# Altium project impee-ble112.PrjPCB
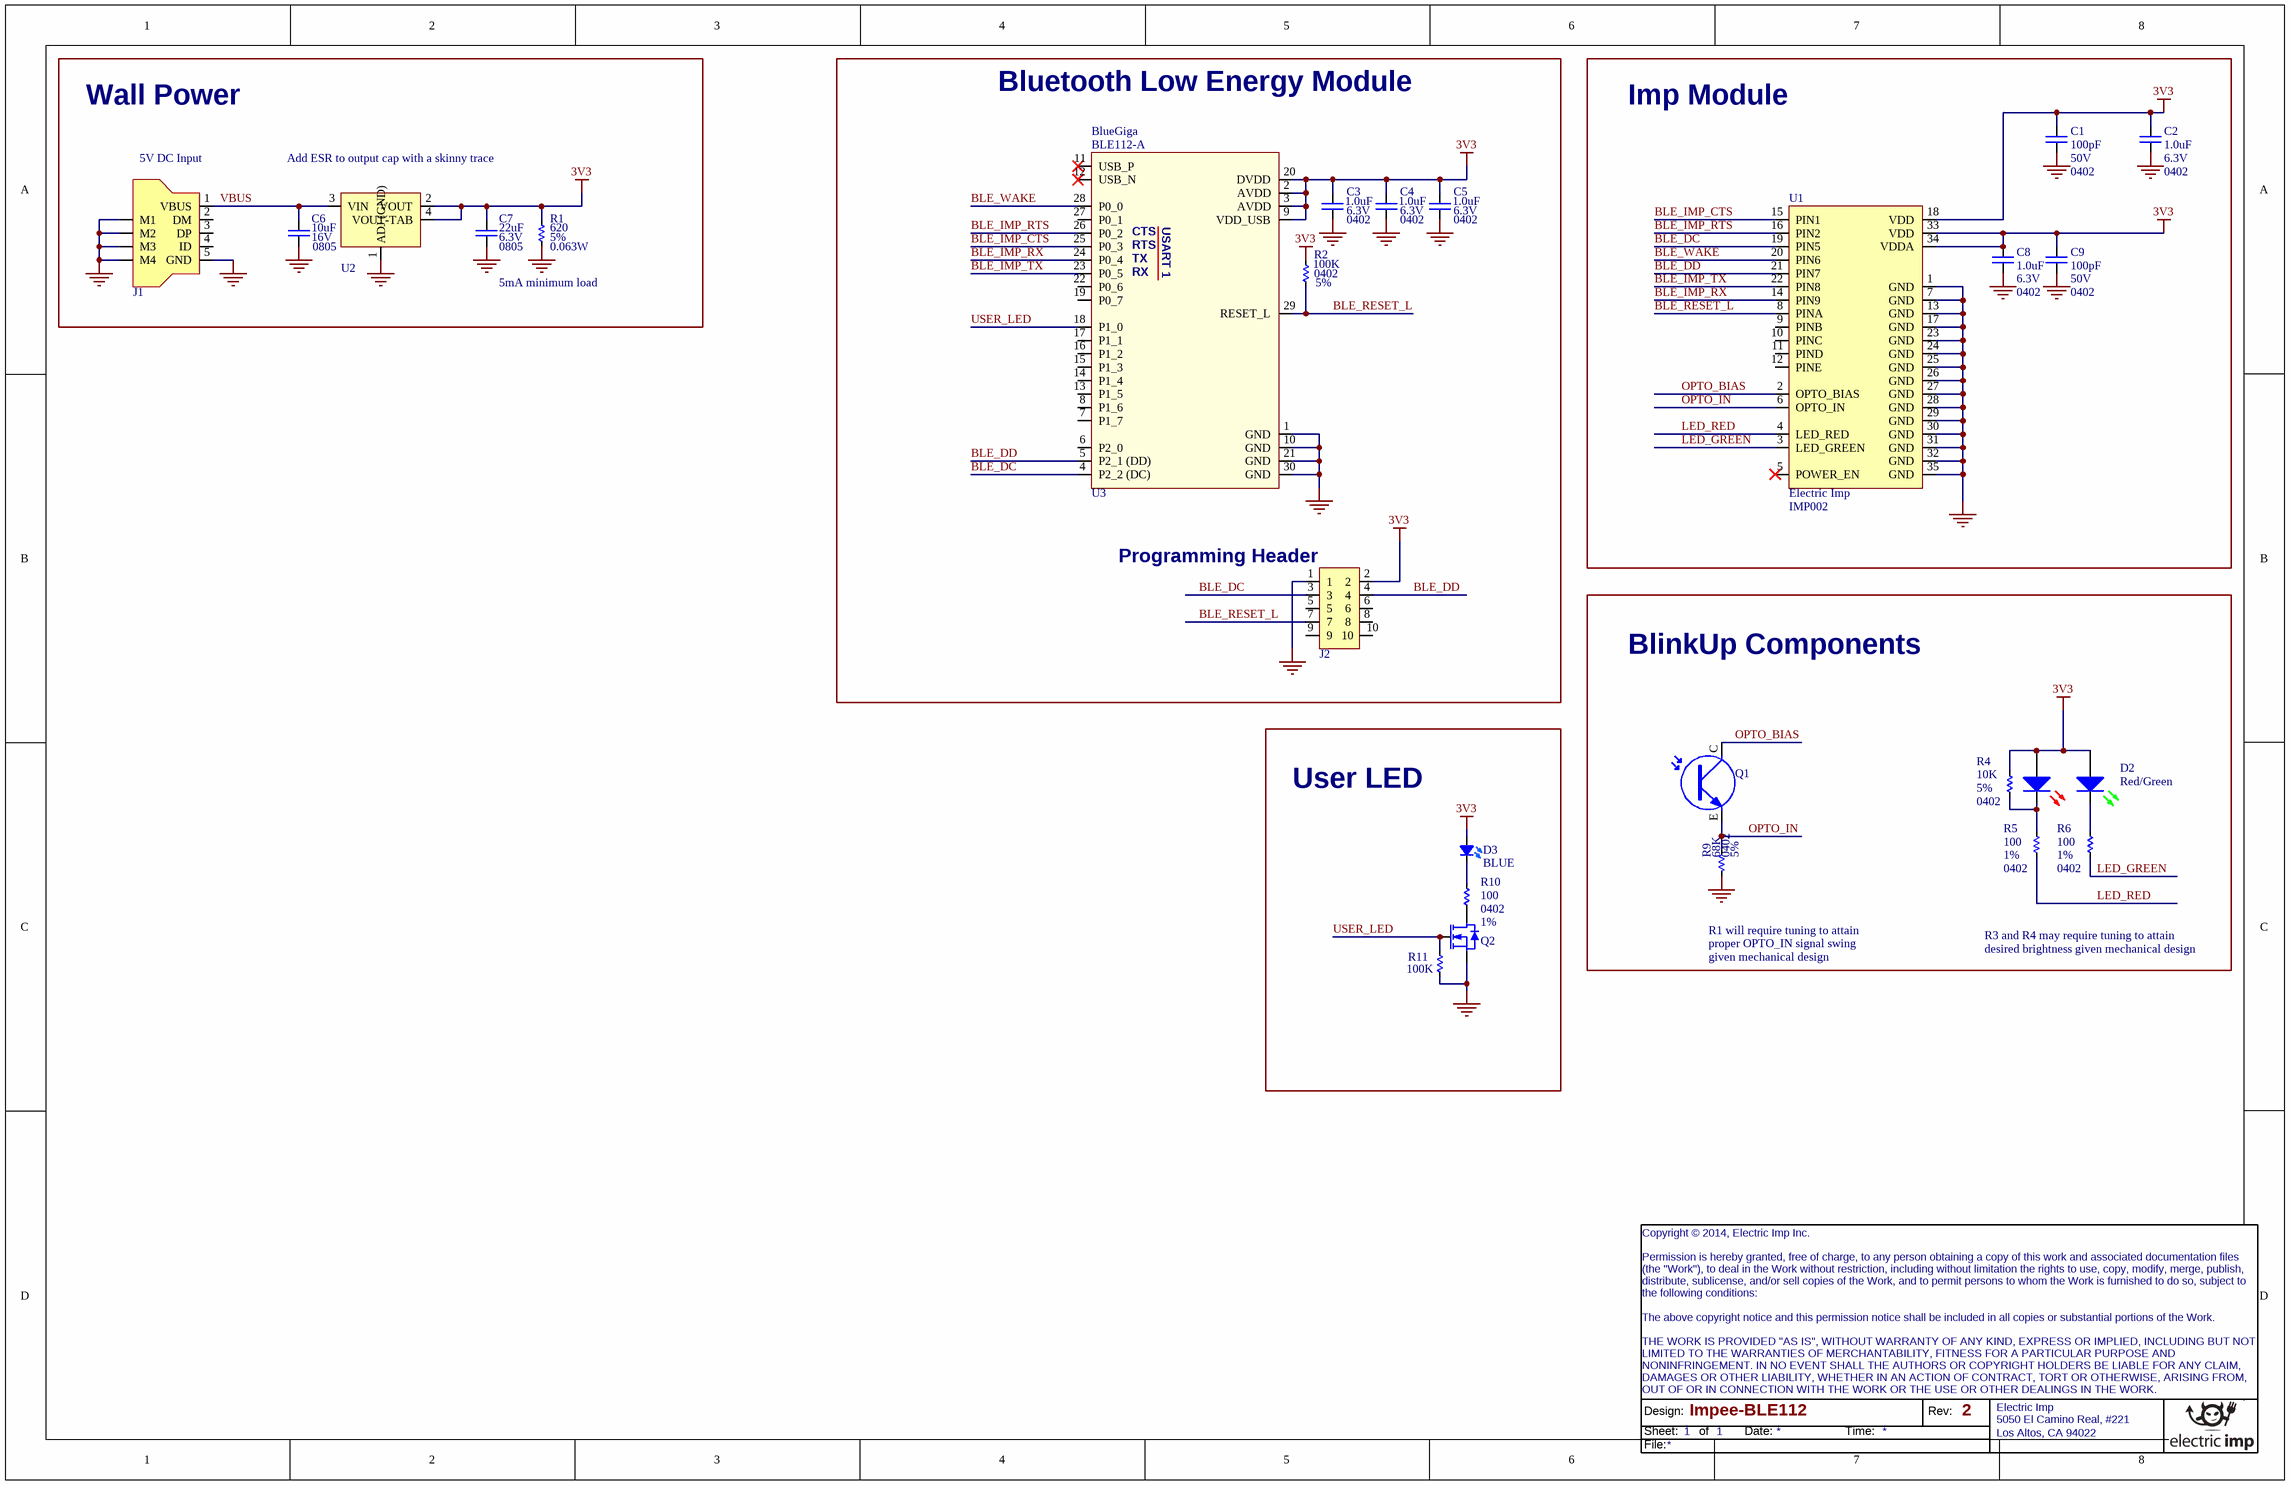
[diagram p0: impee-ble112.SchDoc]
1 sheet, 26 parts. Net scope: global (net labels, ports and power ports of the same name join across sheets).
Board file: impee-ble112.PcbDoc

## Sheet impee-ble112.SchDoc: Impee-BLE112
size Tabloid; Revision: 2; SheetNumber: 1; SheetTotal: 1

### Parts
C1  value 100pF  Voltage: 50V  Package: 0402  [CAPC1005X07N]  (hidden comment: Ceramic Capacitor)
C2  value 1.0uF  Voltage: 6.3V  Package: 0402  [CAPC1005X07N]  (hidden comment: Ceramic Capacitor)
C3  value 1.0uF  Voltage: 6.3V  Package: 0402  [CAPC1005X07N]  (hidden comment: Ceramic Capacitor)
C4  value 1.0uF  Voltage: 6.3V  Package: 0402  [CAPC1005X07N]  (hidden comment: Ceramic Capacitor)
C5  value 1.0uF  Voltage: 6.3V  Package: 0402  [CAPC1005X07N]  (hidden comment: Ceramic Capacitor)
C6  value 10uF  Voltage: 16V  Package: 0805  [CAPC2012X14N]  (hidden comment: Ceramic Capacitor)
C7  value 22uF  Voltage: 6.3V  Package: 0805  [CAPC2012X14N]  (hidden comment: Ceramic Capacitor)
C8  value 1.0uF  Voltage: 6.3V  Package: 0402  [CAPC1005X07N]  (hidden comment: Ceramic Capacitor)
C9  value 100pF  Voltage: 50V  Package: 0402  [CAPC1005X07N]  (hidden comment: Ceramic Capacitor)
D2  Color: Red/Green  [LED1616X07N-REDGREEN]  (hidden comment: LED Red and Green)
D3  Color: BLUE  [LED1608X08N-BLUE]  (hidden comment: LED Blue)
J1  USB Mini/Micro-B  [4UCON20035]  (value not drawn)
J2  Header  [HDR127P2X5-N]  (value not drawn)
Q1  PHOTOTRANSISTOR  [PHOTOTRANS2012X13]  (value not drawn)
Q2  N-Channel MOSFET  [SOT95P300X130-3N]  (value not drawn)
R1  value 620  Tolerance: 5%  Power: 0.063W  [RESC1005X04N]  (hidden comment: Resistor)
R2  value 100K  Package: 0402  Tolerance: 5%  [RESC1005X04N]  (hidden comment: Resistor)
R4  value 10K  Package: 0402  Tolerance: 5%  [RESC1005X04N]  (hidden comment: Resistor)
R5  value 100  Package: 0402  Tolerance: 1%  [RESC1005X04N]  (hidden comment: Resistor)
R6  value 100  Package: 0402  Tolerance: 1%  [RESC1005X04N]  (hidden comment: Resistor)
R9  value 68K  Package: 0402  Tolerance: 5%  [RESC1005X04N]  (hidden comment: Resistor)
R10  value 100  Package: 0402  Tolerance: 1%  [RESC1005X04N]  (hidden comment: Resistor)
R11  value 100K  [RESC1005X04N]  (hidden comment: Resistor)
U1  Manufacturer: Electric Imp  Manufacturer Part Number: IMP002  [IMP_MODULE]  (hidden comment: imp module)
U2  AP1117  [SOT230P700X180-4N]  (value not drawn)
U3  Manufacturer: BlueGiga  Manufacturer Part Number: BLE112-A  [BLE112]  (hidden comment: BLE112)

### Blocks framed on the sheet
Wall Power: C6 C7 J1 R1 U2
Bluetooth Low Energy Module: C3-C5 J2 R2 U3
Imp Module: C1 C2 C8 C9 U1
BlinkUp Components: D2 Q1 R4-R6 R9
User LED: D3 Q2 R10 R11

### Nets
3V3: C1.2 C2.2 C3.2 C4.2 C5.2 C7.2 C8.2 C9.2 D2.AG D2.AR D3.A J2.2 R1.2 R2.2 R4.2 U1.18(VDD) U1.33(VDD) U1.34(VDDA) U2.2(VOUT) U2.4(VOUT-TAB) U3.2(AVDD) U3.3(AVDD) U3.9(VDD_USB) U3.20(DVDD)
GND: C1.1 C2.1 C3.1 C4.1 C5.1 C6.1 C7.1 C8.1 C9.1 J1.5(GND) J1.M1 J1.M2 J1.M3 J1.M4 J2.1 Q2.2(S) R1.1 R9.1 R11.1 U1.1(GND) U1.7(GND) U1.13(GND) U1.17(GND) U1.23(GND) U1.24(GND) U1.25(GND) U1.26(GND) U1.27(GND) U1.28(GND) U1.29(GND) U1.30(GND) U1.31(GND) U1.32(GND) U1.35(GND) U2.1(ADJ_(GND)) U3.1(GND) U3.10(GND) U3.21(GND) U3.30(GND)
BLE_DC: J2.3 U1.19(PIN5) U3.4(P2_2_(DC))
BLE_DD: J2.4 U1.21(PIN7) U3.5(P2_1_(DD))
BLE_IMP_CTS: U1.15(PIN1) U3.25(P0_3)
BLE_IMP_RTS: U1.16(PIN2) U3.26(P0_2)
BLE_IMP_RX: U1.14(PIN9) U3.24(P0_4)
BLE_IMP_TX: U1.22(PIN8) U3.23(P0_5)
BLE_RESET_L: J2.7 R2.1 U1.8(PINA) U3.29(RESET_L)
BLE_WAKE: U1.20(PIN6) U3.28(P0_0)
LED_GREEN: R6.1 U1.3(LED_GREEN)
LED_RED: R5.1 U1.4(LED_RED)
OPTO_BIAS: Q1.C U1.2(OPTO_BIAS)
OPTO_IN: Q1.E R9.2 U1.6(OPTO_IN)
USER_LED: Q2.1(G) R11.2 U3.18(P1_0)
VBUS: C6.2 J1.1(VBUS) U2.3(VIN)
NetD2_KG: D2.KG R6.2
NetD2_KR: D2.KR R4.1 R5.2
NetD3_K: D3.K R10.2
NetQ2_3: Q2.3(D) R10.1

Not connected (* = marked no-connect by the designer): J1 2(DM) 3(DP) 4(ID); J2 5 6 8 9 10; U1 5(POWER_EN)* 9(PINB) 10(PINC) 11(PIND) 12(PINE); U3 6(P2_0) 7(P1_7) 8(P1_6) 11(USB_P)* 12(USB_N)* 13(P1_5) 14(P1_4) 15(P1_3) 16(P1_2) 17(P1_1) 19(P0_7) 22(P0_6) 27(P0_1)

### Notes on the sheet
- (near J1) 5V DC Input
- Add ESR to output cap with a skinny trace
- (near U3) USART 1
- 5mA minimum load
- (near U3) CTS
- (near U3) RTS
- (near U3) RX
- (near U3) TX
- (near J2) Programming Header
- R1 will require tuning to attain
- proper OPTO_IN signal swing
- given mechanical design
- R3 and R4 may require tuning to attain
- desired brightness given mechanical design

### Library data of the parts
C1 C9 = CAPC00043: CAP,C0G,100pF,5%,50V,0402; Manufacturer: Yageo; Manufacturer Part Number: CC0402JRNPO9BN101
C2 C8 = CAPC00005: CAP,X5R,1.0uF,10%,6.3V, 0402,#; Manufacturer: Taiyo Yuden; Manufacturer Part Number: JMK105BJ105KV-F
C3-C5 = CAPC00005: CAP,X5R,1.0uF,10%,6.3V, 0402,#; Manufacturer: Murata; Manufacturer Part Number: GRM155R60J105KE19D
C6 = CAPC00037: CAP,X5R,10uF,10%,16V,0805,#; Manufacturer: Taiyo Yuden; Manufacturer Part Number: EMK212BJ106KG-T
C7 = CAPC00039: CAP,X5R,22uF,10%,6.3V,0805,#; Manufacturer: TDK; Manufacturer Part Number: C2012X5R0J226K/1.25
D2 = LED00012: LED, Red and Green, 2/2V, 631/571nm, 25/35mcd, SMT; Manufacturer: Liteon; Manufacturer Part Number: LTST-C195KGJRKT; Millicandela Rating (min): 25mcd, 35mcd; Voltage - Forward (Vf) Typ: 2V, 2V; Current - Test: 20mA; Wavelength - Dominant: 631nm, 571nm; Wavelength - Peak: 639nm, 574nm; Viewing Angle: 130°; Lens Type: Clear
D3 = LED00047: LED, Blue, 2.8V, 470nm, 15mcd, 0603; Manufacturer: Liteon; Manufacturer Part Number: LTST-C193TBKT-5A; Current - Test: 5mA; Wavelength - Peak: 468nm; Viewing Angle: 130°; Lens Type: Clear
J1 = USB00001: USB Mini-B Connector; Manufacturer: On Shore; Manufacturer Part Number: USB-M26FTR
J2 = HDR00025: HDR, 2x5,1.27mm pitch, Gold Flash, Vertical, THD; Manufacturer: Sullins; Manufacturer Part Number: GRPB052VWVN-RC; Gender: Male; Connector Type: Unshrouded; Number of Columns: 5; Number of Positions Loaded: 10
Q1 = PHOTO00002: Phototrans, Clear, Top View, 940nm, 0.4V, 1mA, 0805; Manufacturer: Everlight; Manufacturer Part Number: PT17-21C/L41/TR8
Q2 = NFET00002: NFET, 60V, 360mA, SOT23; Manufacturer: NXP; Manufacturer Part Number: 2N7002P,215; Drain to Source Voltage (Vdss): 50V; Rds On (Max) @ Id, Vgs: 1.6 Ohm @ 500mA, 10V; Vgs(th) (Max) @ Id: 2.4V @ 250µA; Power - Max: 350mW
R1 = RES00048: RES,620 Ohm,5%,0.063W,0402; Manufacturer: Yageo; Manufacturer Part Number: RC0402JR-07620RL
R2 = RES00001: RES,100k,5%,0.063W,0402,#; Manufacturer: Samsung; Manufacturer Part Number: RC1005J104CS
R4 = RES00006: RES,10k,5%,0.063W,0402,#; Manufacturer: Stackpole; Manufacturer Part Number: RMCF0402JT10K0
R5 R6 R10 = RES00024: RES,100 Ohm,1%,0.063W,0402,#; Manufacturer: Yageo; Manufacturer Part Number: RC0402FR-07100RL
R9 = RES00052: RES,68K,5%,0.063W,0402#; Manufacturer: Samsung; Manufacturer Part Number: RC1005J683CS
R11 = RES00001: RES,100k,5%,0.063W,0402,#; Manufacturer: Stackpole; Manufacturer Part Number: RMCF0402JT100K
U1 = MOD00002: Module, Electric Imp Solder Down with Antenna
U2 = IC00033: IC, LDO, Fixed 3.3V, 1A, SOT-223; Manufacturer: Diodes Inc.; Manufacturer Part Number: AP1117E33G-13
U3 = MOD00011: Module, BlueGiga BLE112, Bluetooth Low Energy, Built-in Antenna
